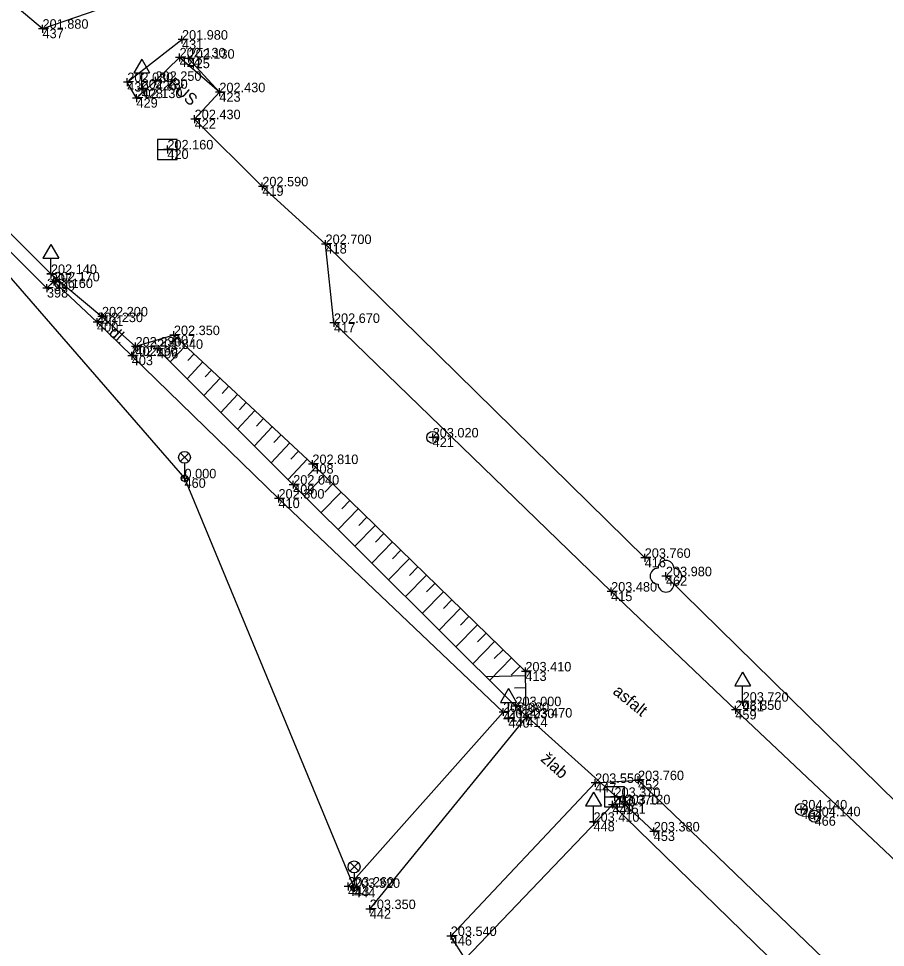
# Model space of a CAD drawing. Extents: x -744883 to -744469, y -966832 to -966374.
# Drawn here: x -744612.5 to -744557.8, y -966750.1 to -966691.4 of the extents above; entities that cross this region are included whole.
import ezdxf

# ---------------------------------------------------------------- set-up
doc = ezdxf.new("R2010")
doc.units = 0
for name, color, linetype in [('Body polohopisu', 7, 'Continuous'), ('Budovy', 7, 'Continuous'), ('Doplňkové značky', 7, 'Continuous'), ('Ploty_opěrné zdi', 7, 'Continuous'), ('Popisy objektů_povrchů', 7, 'Continuous'), ('Rozhraní ploch', 7, 'Continuous'), ('Stromy_porost', 7, 'Continuous'), ('Vrstva 132', 7, 'Continuous'), ('Vstup na pozemek', 7, 'Continuous'), ('Výškopis', 7, 'Continuous'), ('Výšky bodů', 7, 'Continuous'), ('Značky IS', 7, 'Continuous'), ('Čísla bodů', 7, 'Continuous')]:
    doc.layers.add(name, color=color, linetype=linetype)

msp = doc.modelspace()

# ---------------------------------------------------------------- linework, layer by layer
at = {"layer": 'Body polohopisu'}
for p, q in [((-744611.03, -966692.07), (-744611.03, -966691.82)), ((-744611.03, -966692.07), (-744611.28, -966692.07)), ((-744611.03, -966692.07), (-744610.78, -966692.07)), ((-744611.03, -966692.07), (-744611.03, -966692.32)), ((-744602.23, -966692.76), (-744602.23, -966692.51)), ((-744602.23, -966692.76), (-744602.48, -966692.76)), ((-744602.23, -966692.76), (-744601.98, -966692.76)), ((-744602.23, -966692.76), (-744602.23, -966693.01)), ((-744602.38, -966693.88), (-744602.38, -966693.63)), ((-744601.81, -966693.96), (-744601.81, -966693.71)), ((-744602.38, -966693.88), (-744602.63, -966693.88)), ((-744602.38, -966693.88), (-744602.13, -966693.88)), ((-744602.38, -966693.88), (-744602.38, -966694.13)), ((-744601.81, -966693.96), (-744602.06, -966693.96)), ((-744601.81, -966693.96), (-744601.56, -966693.96)), ((-744601.81, -966693.96), (-744601.81, -966694.21)), ((-744605.68, -966695.44), (-744605.93, -966695.44)), ((-744605.68, -966695.44), (-744605.68, -966695.19)), ((-744605.68, -966695.44), (-744605.43, -966695.44)), ((-744605.68, -966695.44), (-744605.68, -966695.69)), ((-744603.9, -966695.36), (-744604.15, -966695.36)), ((-744603.9, -966695.36), (-744603.9, -966695.11)), ((-744603.9, -966695.36), (-744603.65, -966695.36)), ((-744603.9, -966695.36), (-744603.9, -966695.61)), ((-744604.77, -966695.86), (-744605.02, -966695.86)), ((-744604.77, -966695.86), (-744604.77, -966695.61)), ((-744604.77, -966695.86), (-744604.52, -966695.86)), ((-744604.77, -966695.86), (-744604.77, -966696.11)), ((-744599.87, -966696.08), (-744600.12, -966696.08)), ((-744599.87, -966696.08), (-744599.87, -966695.83)), ((-744599.87, -966696.08), (-744599.62, -966696.08)), ((-744599.87, -966696.08), (-744599.87, -966696.33)), ((-744605.1, -966696.45), (-744605.35, -966696.45)), ((-744605.1, -966696.45), (-744605.1, -966696.2)), ((-744605.1, -966696.45), (-744604.85, -966696.45)), ((-744605.1, -966696.45), (-744605.1, -966696.7)), ((-744601.43, -966697.78), (-744601.68, -966697.78)), ((-744601.43, -966697.78), (-744601.43, -966697.53)), ((-744601.43, -966697.78), (-744601.18, -966697.78)), ((-744601.43, -966697.78), (-744601.43, -966698.03)), ((-744603.15, -966699.69), (-744603.15, -966699.44)), ((-744603.15, -966699.69), (-744603.4, -966699.69)), ((-744603.15, -966699.69), (-744602.9, -966699.69)), ((-744603.15, -966699.69), (-744603.15, -966699.94)), ((-744597.16, -966702.02), (-744597.16, -966701.77)), ((-744597.16, -966702.02), (-744597.41, -966702.02)), ((-744597.16, -966702.02), (-744596.91, -966702.02)), ((-744597.16, -966702.02), (-744597.16, -966702.27)), ((-744593.17, -966705.66), (-744593.17, -966705.41)), ((-744593.17, -966705.66), (-744593.42, -966705.66)), ((-744593.17, -966705.66), (-744592.92, -966705.66)), ((-744593.17, -966705.66), (-744593.17, -966705.91)), ((-744610.5, -966707.55), (-744610.75, -966707.55)), ((-744610.5, -966707.55), (-744610.5, -966707.3)), ((-744610.5, -966707.55), (-744610.25, -966707.55)), ((-744610.5, -966707.55), (-744610.5, -966707.8)), ((-744610.32, -966708.02), (-744610.32, -966707.77)), ((-744610.75, -966708.44), (-744611, -966708.44)), ((-744610.75, -966708.44), (-744610.75, -966708.19)), ((-744610.75, -966708.44), (-744610.5, -966708.44)), ((-744610.75, -966708.44), (-744610.75, -966708.69)), ((-744610.32, -966708.02), (-744610.57, -966708.02)), ((-744610.32, -966708.02), (-744610.07, -966708.02)), ((-744610.32, -966708.02), (-744610.32, -966708.27)), ((-744607.28, -966710.23), (-744607.28, -966709.98)), ((-744607.59, -966710.59), (-744607.84, -966710.59)), ((-744607.59, -966710.59), (-744607.59, -966710.34)), ((-744607.59, -966710.59), (-744607.34, -966710.59)), ((-744607.59, -966710.59), (-744607.59, -966710.84)), ((-744607.28, -966710.23), (-744607.53, -966710.23)), ((-744607.28, -966710.23), (-744607.03, -966710.23)), ((-744607.28, -966710.23), (-744607.28, -966710.48)), ((-744592.64, -966710.64), (-744592.89, -966710.64)), ((-744592.64, -966710.64), (-744592.64, -966710.39)), ((-744592.64, -966710.64), (-744592.39, -966710.64)), ((-744592.64, -966710.64), (-744592.64, -966710.89)), ((-744602.74, -966711.41), (-744602.74, -966711.16)), ((-744605.16, -966712.13), (-744605.16, -966711.88)), ((-744602.74, -966711.41), (-744602.99, -966711.41)), ((-744602.74, -966711.41), (-744602.49, -966711.41)), ((-744602.74, -966711.41), (-744602.74, -966711.66)), ((-744605.16, -966712.13), (-744605.41, -966712.13)), ((-744605.4, -966712.71), (-744605.4, -966712.46)), ((-744605.16, -966712.13), (-744604.91, -966712.13)), ((-744605.16, -966712.13), (-744605.16, -966712.38)), ((-744603.8, -966712.28), (-744604.05, -966712.28)), ((-744603.8, -966712.28), (-744603.8, -966712.03)), ((-744603.8, -966712.28), (-744603.55, -966712.28)), ((-744603.8, -966712.28), (-744603.8, -966712.53)), ((-744605.4, -966712.71), (-744605.65, -966712.71)), ((-744605.4, -966712.71), (-744605.15, -966712.71)), ((-744605.4, -966712.71), (-744605.4, -966712.96)), ((-744586.41, -966717.87), (-744586.41, -966717.62)), ((-744586.41, -966717.87), (-744586.66, -966717.87)), ((-744586.41, -966717.87), (-744586.16, -966717.87)), ((-744586.41, -966717.87), (-744586.41, -966718.12)), ((-744594, -966719.55), (-744594.25, -966719.55)), ((-744594, -966719.55), (-744594, -966719.3)), ((-744594, -966719.55), (-744593.75, -966719.55)), ((-744594, -966719.55), (-744594, -966719.8)), ((-744602.07, -966720.45), (-744602.32, -966720.45)), ((-744602.07, -966720.45), (-744602.07, -966720.2)), ((-744602.07, -966720.45), (-744601.82, -966720.45)), ((-744602.07, -966720.45), (-744602.07, -966720.7)), ((-744595.21, -966720.85), (-744595.21, -966720.6)), ((-744595.21, -966720.85), (-744595.46, -966720.85)), ((-744595.21, -966720.85), (-744594.96, -966720.85)), ((-744595.21, -966720.85), (-744595.21, -966721.1)), ((-744596.14, -966721.73), (-744596.39, -966721.73)), ((-744596.14, -966721.73), (-744596.14, -966721.48)), ((-744596.14, -966721.73), (-744595.89, -966721.73)), ((-744596.14, -966721.73), (-744596.14, -966721.98)), ((-744573.03, -966725.47), (-744573.03, -966725.22)), ((-744573.03, -966725.47), (-744573.28, -966725.47)), ((-744573.03, -966725.47), (-744572.78, -966725.47)), ((-744573.03, -966725.47), (-744573.03, -966725.72)), ((-744571.69, -966726.63), (-744571.69, -966726.38)), ((-744571.69, -966726.63), (-744571.94, -966726.63)), ((-744571.69, -966726.63), (-744571.44, -966726.63)), ((-744571.69, -966726.63), (-744571.69, -966726.88)), ((-744575.15, -966727.6), (-744575.4, -966727.6)), ((-744575.15, -966727.6), (-744575.15, -966727.35)), ((-744575.15, -966727.6), (-744574.9, -966727.6)), ((-744575.15, -966727.6), (-744575.15, -966727.85)), ((-744580.56, -966732.64), (-744580.56, -966732.39)), ((-744580.56, -966732.64), (-744580.81, -966732.64)), ((-744580.56, -966732.64), (-744580.31, -966732.64)), ((-744580.56, -966732.64), (-744580.56, -966732.89)), ((-744581.19, -966734.83), (-744581.19, -966734.58)), ((-744567.31, -966735.07), (-744567.31, -966734.82)), ((-744566.85, -966734.55), (-744567.1, -966734.55)), ((-744566.85, -966734.55), (-744566.85, -966734.3)), ((-744566.85, -966734.55), (-744566.6, -966734.55)), ((-744566.85, -966734.55), (-744566.85, -966734.8)), ((-744581.96, -966735.2), (-744582.21, -966735.2)), ((-744581.96, -966735.2), (-744581.96, -966734.95)), ((-744581.96, -966735.2), (-744581.71, -966735.2)), ((-744581.96, -966735.2), (-744581.96, -966735.45)), ((-744581.63, -966735.59), (-744581.63, -966735.34)), ((-744581.19, -966734.83), (-744581.44, -966734.83)), ((-744581.19, -966734.83), (-744580.94, -966734.83)), ((-744581.19, -966734.83), (-744581.19, -966735.08)), ((-744580.5, -966735.55), (-744580.5, -966735.3)), ((-744567.31, -966735.07), (-744567.56, -966735.07)), ((-744567.31, -966735.07), (-744567.06, -966735.07)), ((-744567.31, -966735.07), (-744567.31, -966735.32)), ((-744581.63, -966735.59), (-744581.88, -966735.59)), ((-744581.63, -966735.59), (-744581.38, -966735.59)), ((-744581.63, -966735.59), (-744581.63, -966735.84)), ((-744580.5, -966735.55), (-744580.75, -966735.55)), ((-744580.5, -966735.55), (-744580.25, -966735.55)), ((-744580.5, -966735.55), (-744580.5, -966735.8)), ((-744576.16, -966739.68), (-744576.16, -966739.43)), ((-744573.45, -966739.5), (-744573.7, -966739.5)), ((-744573.45, -966739.5), (-744573.45, -966739.25)), ((-744573.45, -966739.5), (-744573.2, -966739.5)), ((-744573.45, -966739.5), (-744573.45, -966739.75)), ((-744576.16, -966739.68), (-744576.41, -966739.68)), ((-744576.16, -966739.68), (-744575.91, -966739.68)), ((-744576.16, -966739.68), (-744576.16, -966739.93)), ((-744574.94, -966740.56), (-744575.19, -966740.56)), ((-744574.94, -966740.56), (-744574.94, -966740.31)), ((-744574.94, -966740.56), (-744574.69, -966740.56)), ((-744574.94, -966740.56), (-744574.94, -966740.81)), ((-744575.07, -966741.05), (-744575.32, -966741.05)), ((-744575.07, -966741.05), (-744575.07, -966740.8)), ((-744575.07, -966741.05), (-744574.82, -966741.05)), ((-744575.07, -966741.05), (-744575.07, -966741.3)), ((-744574.31, -966741.02), (-744574.56, -966741.02)), ((-744574.31, -966741.02), (-744574.31, -966740.77)), ((-744574.31, -966741.02), (-744574.06, -966741.02)), ((-744574.31, -966741.02), (-744574.31, -966741.27)), ((-744563.15, -966741.35), (-744563.15, -966741.1)), ((-744563.15, -966741.35), (-744563.4, -966741.35)), ((-744563.15, -966741.35), (-744562.9, -966741.35)), ((-744563.15, -966741.35), (-744563.15, -966741.6)), ((-744562.31, -966741.78), (-744562.56, -966741.78)), ((-744562.31, -966741.78), (-744562.31, -966741.53)), ((-744562.31, -966741.78), (-744562.06, -966741.78)), ((-744562.31, -966741.78), (-744562.31, -966742.03)), ((-744576.26, -966742.13), (-744576.51, -966742.13)), ((-744576.26, -966742.13), (-744576.26, -966741.88)), ((-744576.26, -966742.13), (-744576.01, -966742.13)), ((-744576.26, -966742.13), (-744576.26, -966742.38)), ((-744572.46, -966742.74), (-744572.71, -966742.74)), ((-744572.46, -966742.74), (-744572.46, -966742.49)), ((-744572.46, -966742.74), (-744572.21, -966742.74)), ((-744572.46, -966742.74), (-744572.46, -966742.99)), ((-744591.75, -966746.22), (-744592, -966746.22)), ((-744591.75, -966746.22), (-744591.75, -966745.97)), ((-744591.75, -966746.22), (-744591.5, -966746.22)), ((-744591.75, -966746.22), (-744591.75, -966746.47)), ((-744591.37, -966746.3), (-744591.62, -966746.3)), ((-744591.37, -966746.3), (-744591.37, -966746.05)), ((-744591.37, -966746.3), (-744591.12, -966746.3)), ((-744591.37, -966746.3), (-744591.37, -966746.55)), ((-744590.38, -966747.64), (-744590.63, -966747.64)), ((-744590.38, -966747.64), (-744590.38, -966747.39)), ((-744590.38, -966747.64), (-744590.13, -966747.64)), ((-744590.38, -966747.64), (-744590.38, -966747.89)), ((-744585.27, -966749.34), (-744585.52, -966749.34)), ((-744585.27, -966749.34), (-744585.27, -966749.09)), ((-744585.27, -966749.34), (-744585.02, -966749.34)), ((-744585.27, -966749.34), (-744585.27, -966749.59))]:
    msp.add_line(p, q, dxfattribs=at)
at = {"layer": 'Budovy'}
msp.add_lwpolyline([(-744601.43, -966697.78), (-744599.87, -966696.08), (-744602.38, -966693.88), (-744603.9, -966695.36)], dxfattribs=at)
at = {"layer": 'Doplňkové značky'}
for p, q in [((-744604.77, -966693.994), (-744605.27, -966694.86)), ((-744604.77, -966693.994), (-744604.27, -966694.86)), ((-744605.27, -966694.86), (-744604.27, -966694.86)), ((-744604.77, -966695.86), (-744604.77, -966694.86)), ((-744605.02, -966695.86), (-744604.52, -966695.86)), ((-744610.5, -966705.684), (-744611, -966706.55)), ((-744610.5, -966705.684), (-744610, -966706.55)), ((-744611, -966706.55), (-744610, -966706.55)), ((-744610.5, -966707.55), (-744610.5, -966706.55)), ((-744610.75, -966707.55), (-744610.25, -966707.55)), ((-744602.334, -966719.388), (-744601.806, -966718.86)), ((-744601.798, -966719.385), (-744602.326, -966718.856)), ((-744602.07, -966719.5), (-744602.07, -966720.25)), ((-744566.85, -966732.684), (-744567.35, -966733.55)), ((-744566.85, -966732.684), (-744566.35, -966733.55)), ((-744567.35, -966733.55), (-744566.35, -966733.55)), ((-744566.85, -966734.55), (-744566.85, -966733.55)), ((-744581.63, -966733.724), (-744582.13, -966734.59)), ((-744581.63, -966733.724), (-744581.13, -966734.59)), ((-744582.13, -966734.59), (-744581.13, -966734.59)), ((-744581.63, -966735.59), (-744581.63, -966734.59)), ((-744567.1, -966734.55), (-744566.6, -966734.55)), ((-744581.88, -966735.59), (-744581.38, -966735.59)), ((-744576.26, -966740.264), (-744576.76, -966741.13)), ((-744576.26, -966740.264), (-744575.76, -966741.13)), ((-744576.76, -966741.13), (-744575.76, -966741.13)), ((-744576.26, -966742.13), (-744576.26, -966741.13)), ((-744576.51, -966742.13), (-744576.01, -966742.13)), ((-744591.634, -966745.238), (-744591.106, -966744.71)), ((-744591.098, -966745.235), (-744591.626, -966744.706)), ((-744591.37, -966745.35), (-744591.37, -966746.1))]:
    msp.add_line(p, q, dxfattribs=at)
for centre, radius in [((-744602.07, -966719.125), 0.375), ((-744602.07, -966720.45), 0.2), ((-744591.37, -966744.975), 0.375), ((-744591.37, -966746.3), 0.2)]:
    msp.add_circle(centre, radius, dxfattribs=at)
at = {"layer": 'Ploty_opěrné zdi'}
for points in [[(-744599.87, -966696.08), (-744601.81, -966693.96)], [(-744627.59, -966697.13), (-744622.55, -966697.44), (-744620.91, -966698.33), (-744610.75, -966708.44)], [(-744597.16, -966702.02), (-744601.43, -966697.78)], [(-744573.03, -966725.47), (-744593.17, -966705.66)], [(-744610.75, -966708.44), (-744610.32, -966708.02), (-744607.59, -966710.59)], [(-744605.4, -966712.71), (-744596.14, -966721.73)], [(-744596.14, -966721.73), (-744581.96, -966735.2), (-744591.75, -966746.22)], [(-744571.69, -966726.63), (-744555.99, -966742.05)], [(-744584.36, -966750.78), (-744575.07, -966741.05), (-744562.79, -966753.02)]]:
    msp.add_lwpolyline(points, dxfattribs=at)
at = {"layer": 'Rozhraní ploch'}
for points in [[(-744606.2, -966690.42), (-744611.03, -966692.07), (-744618.42, -966685.85), (-744624.38, -966680.12), (-744632.56, -966672.44)], [(-744603.9, -966695.36), (-744605.1, -966696.45), (-744605.68, -966695.44), (-744602.23, -966692.76)], [(-744627.59, -966697.13), (-744627.42, -966696.08), (-744623.89, -966695.45), (-744621.28, -966696.76), (-744621.28, -966696.76), (-744610.5, -966707.55), (-744607.28, -966710.23)], [(-744484.45, -966802.29), (-744488.93, -966807.11), (-744494.18, -966806.31), (-744504.16, -966796.59), (-744523.84, -966777.07), (-744535.89, -966765.33), (-744540.85, -966760.58), (-744553.38, -966748.22), (-744567.31, -966735.07), (-744575.15, -966727.6), (-744592.64, -966710.64), (-744593.17, -966705.66)], [(-744607.59, -966710.59), (-744607.28, -966710.23), (-744605.16, -966712.13)], [(-744590.38, -966747.64), (-744580.5, -966735.55), (-744580.56, -966732.64), (-744594, -966719.55), (-744602.74, -966711.41), (-744605.16, -966712.13), (-744605.4, -966712.71)], [(-744581.19, -966734.83), (-744574.31, -966741.02)], [(-744584.36, -966750.78), (-744585.27, -966749.34), (-744576.16, -966739.68), (-744573.45, -966739.5), (-744561.19, -966751.3), (-744536.79, -966774.59), (-744538.25, -966777.52)]]:
    msp.add_lwpolyline(points, dxfattribs=at)
at = {"layer": 'Stromy_porost'}
msp.add_circle((-744571.69, -966726.63), 0.0005, dxfattribs=at)
for centre, start, end in [((-744571.69, -966726.13), 0, 179.99999), ((-744572.19, -966726.63), 89.99999, 269.99999), ((-744571.19, -966726.63), 270, 89.99999), ((-744571.69, -966727.13), 179.99999, 359.99999)]:
    msp.add_arc(centre, 0.5, start, end, dxfattribs=at)
at = {"layer": 'Vrstva 132'}
msp.add_lwpolyline([(-744622.6, -966696.82), (-744602.07, -966720.45), (-744591.37, -966746.3)], dxfattribs=at)
at = {"layer": 'Vstup na pozemek'}
for points in [[(-744593.17, -966705.66), (-744597.16, -966702.02)], [(-744607.59, -966710.59), (-744605.4, -966712.71)]]:
    msp.add_lwpolyline(points, dxfattribs=at)
at = {"layer": 'Výškopis'}
for points in [[(-744603.951, -966711.77), (-744603.891, -966711.974)], [(-744602.567, -966711.571), (-744602.942, -966711.973)], [(-744603.8, -966712.28), (-744595.21, -966720.85), (-744581.19, -966734.83)], [(-744602.018, -966712.082), (-744602.972, -966713.106)], [(-744600.921, -966713.104), (-744601.909, -966714.166)], [(-744601.47, -966712.593), (-744601.858, -966713.01)], [(-744600.372, -966713.616), (-744600.774, -966714.048)], [(-744599.823, -966714.127), (-744600.847, -966715.226)], [(-744599.274, -966714.638), (-744599.691, -966715.085)], [(-744598.725, -966715.149), (-744599.784, -966716.286)], [(-744598.177, -966715.66), (-744598.607, -966716.123)], [(-744597.628, -966716.171), (-744598.722, -966717.346)], [(-744596.53, -966717.194), (-744597.659, -966718.406)], [(-744597.079, -966716.683), (-744597.524, -966717.16)], [(-744595.981, -966717.705), (-744596.44, -966718.197)], [(-744595.432, -966718.216), (-744596.597, -966719.466)], [(-744594.884, -966718.727), (-744595.356, -966719.235)], [(-744594.335, -966719.238), (-744595.534, -966720.526)], [(-744593.79, -966719.754), (-744594.287, -966720.264)], [(-744593.253, -966720.277), (-744594.5, -966721.558)], [(-744592.179, -966721.324), (-744593.438, -966722.617)], [(-744592.716, -966720.801), (-744593.217, -966721.315)], [(-744591.641, -966721.847), (-744592.147, -966722.367)], [(-744591.104, -966722.371), (-744592.376, -966723.676)], [(-744590.567, -966722.894), (-744591.078, -966723.419)], [(-744590.029, -966723.417), (-744591.313, -966724.736)], [(-744589.492, -966723.941), (-744590.008, -966724.47)], [(-744588.955, -966724.464), (-744590.251, -966725.795)], [(-744588.418, -966724.987), (-744588.939, -966725.522)], [(-744587.88, -966725.51), (-744589.189, -966726.854)], [(-744586.806, -966726.557), (-744588.127, -966727.913)], [(-744587.343, -966726.034), (-744587.869, -966726.574)], [(-744586.268, -966727.08), (-744586.799, -966727.625)], [(-744585.731, -966727.604), (-744587.064, -966728.972)], [(-744585.194, -966728.127), (-744585.73, -966728.677)], [(-744584.657, -966728.65), (-744586.002, -966730.032)], [(-744584.119, -966729.173), (-744584.66, -966729.729)], [(-744583.582, -966729.697), (-744584.94, -966731.091)], [(-744583.045, -966730.22), (-744583.59, -966730.78)], [(-744582.507, -966730.743), (-744583.878, -966732.15)], [(-744581.97, -966731.267), (-744582.521, -966731.832)], [(-744581.433, -966731.79), (-744582.815, -966733.209)], [(-744580.896, -966732.313), (-744581.451, -966732.883)], [(-744580.554, -966732.921), (-744583.052, -966732.973)], [(-744580.539, -966733.671), (-744581.249, -966733.686)], [(-744574.31, -966741.02), (-744572.46, -966742.74)]]:
    msp.add_lwpolyline(points, dxfattribs=at)
at = {"layer": 'Značky IS'}
for p, q in [((-744603.775, -966699.689), (-744602.525, -966699.689)), ((-744575.566, -966740.559), (-744574.316, -966740.559))]:
    msp.add_line(p, q, dxfattribs=at)
for points in [[(-744603.775, -966700.317), (-744602.524, -966700.317), (-744602.524, -966699.063), (-744603.775, -966699.063)], [(-744575.566, -966741.187), (-744574.314, -966741.187), (-744574.314, -966739.933), (-744575.566, -966739.933)]]:
    msp.add_lwpolyline(points, close=True, dxfattribs=at)
for centre in [(-744586.41, -966717.87), (-744563.15, -966741.35), (-744562.31, -966741.78)]:
    msp.add_circle(centre, 0.375, dxfattribs=at)

# ---------------------------------------------------------------- texts
at = {"layer": 'Popisy objektů_povrchů'}
for s, rotation, p in [('BUS', 318.76563, (-744603.213, -966695.629)), ('dl.', 318.13247, (-744606.899, -966711.339)), ('asfalt', 320.63174, (-744575.094, -966734)), ('žlab', 318.02199, (-744579.649, -966738.235))]:
    msp.add_text(s, height=0.75, rotation=rotation, dxfattribs=at).set_placement(p)
at = {"layer": 'Výšky bodů'}
for s, p in [('201.880', (-744611.03, -966692.07)), ('201.980', (-744602.23, -966692.76)), ('202.130', (-744602.38, -966693.88)), ('202.130', (-744601.81, -966693.96)), ('202.080', (-744605.68, -966695.44)), ('202.250', (-744603.9, -966695.36)), ('202.230', (-744604.77, -966695.86)), ('202.430', (-744599.87, -966696.08)), ('202.130', (-744605.1, -966696.45)), ('202.430', (-744601.43, -966697.78)), ('202.160', (-744603.15, -966699.69)), ('202.590', (-744597.16, -966702.02)), ('202.700', (-744593.17, -966705.66)), ('202.140', (-744610.5, -966707.55)), ('202.160', (-744610.75, -966708.44)), ('202.170', (-744610.32, -966708.02)), ('202.230', (-744607.59, -966710.59)), ('202.200', (-744607.28, -966710.23)), ('202.670', (-744592.64, -966710.64)), ('202.350', (-744602.74, -966711.41)), ('202.230', (-744605.16, -966712.13)), ('201.840', (-744603.8, -966712.28)), ('202.190', (-744605.4, -966712.71)), ('203.020', (-744586.41, -966717.87)), ('202.810', (-744594, -966719.55)), ('0.000', (-744602.07, -966720.45)), ('202.040', (-744595.21, -966720.85)), ('202.300', (-744596.14, -966721.73)), ('203.760', (-744573.03, -966725.47)), ('203.980', (-744571.69, -966726.63)), ('203.480', (-744575.15, -966727.6)), ('203.410', (-744580.56, -966732.64)), ('203.000', (-744581.19, -966734.83)), ('203.720', (-744566.85, -966734.55)), ('203.080', (-744581.96, -966735.2)), ('203.850', (-744567.31, -966735.07)), ('203.230', (-744581.63, -966735.59)), ('203.470', (-744580.5, -966735.55)), ('203.760', (-744573.45, -966739.5)), ('203.550', (-744576.16, -966739.68)), ('203.370', (-744574.94, -966740.56)), ('203.370', (-744575.07, -966741.05)), ('203.120', (-744574.31, -966741.02)), ('204.140', (-744563.15, -966741.35)), ('204.140', (-744562.31, -966741.78)), ('203.410', (-744576.26, -966742.13)), ('203.380', (-744572.46, -966742.74)), ('203.260', (-744591.75, -966746.22)), ('203.320', (-744591.37, -966746.3)), ('203.350', (-744590.38, -966747.64)), ('203.540', (-744585.27, -966749.34))]:
    msp.add_text(s, height=0.6, dxfattribs=at).set_placement(p)
at = {"layer": 'Čísla bodů'}
for s, p in [('437', (-744611.03, -966692.67)), ('431', (-744602.23, -966693.36)), ('424', (-744602.38, -966694.48)), ('425', (-744601.81, -966694.56)), ('430', (-744605.68, -966696.04)), ('426', (-744603.9, -966695.96)), ('428', (-744604.77, -966696.46)), ('423', (-744599.87, -966696.68)), ('429', (-744605.1, -966697.05)), ('422', (-744601.43, -966698.38)), ('420', (-744603.15, -966700.29)), ('419', (-744597.16, -966702.62)), ('418', (-744593.17, -966706.26)), ('397', (-744610.5, -966708.15)), ('398', (-744610.75, -966709.04)), ('399', (-744610.32, -966708.62)), ('400', (-744607.59, -966711.19)), ('401', (-744607.28, -966710.83)), ('417', (-744592.64, -966711.24)), ('407', (-744602.74, -966712.01)), ('402', (-744605.16, -966712.73)), ('406', (-744603.8, -966712.88)), ('403', (-744605.4, -966713.31)), ('421', (-744586.41, -966718.47)), ('408', (-744594, -966720.15)), ('460', (-744602.07, -966721.05)), ('409', (-744595.21, -966721.45)), ('410', (-744596.14, -966722.33)), ('416', (-744573.03, -966726.07)), ('462', (-744571.69, -966727.23)), ('415', (-744575.15, -966728.2)), ('413', (-744580.56, -966733.24)), ('412', (-744581.19, -966735.43)), ('461', (-744566.85, -966735.15)), ('411', (-744581.96, -966735.8)), ('459', (-744567.31, -966735.67)), ('440', (-744581.63, -966736.19)), ('414', (-744580.5, -966736.15)), ('452', (-744573.45, -966740.1)), ('447', (-744576.16, -966740.28)), ('450', (-744574.94, -966741.16)), ('449', (-744575.07, -966741.65)), ('451', (-744574.31, -966741.62)), ('467', (-744563.15, -966741.95)), ('466', (-744562.31, -966742.38)), ('448', (-744576.26, -966742.73)), ('453', (-744572.46, -966743.34)), ('443', (-744591.75, -966746.82)), ('444', (-744591.37, -966746.9)), ('442', (-744590.38, -966748.24)), ('446', (-744585.27, -966749.94))]:
    msp.add_text(s, height=0.6, dxfattribs=at).set_placement(p)

doc.saveas('drawing.dxf')
